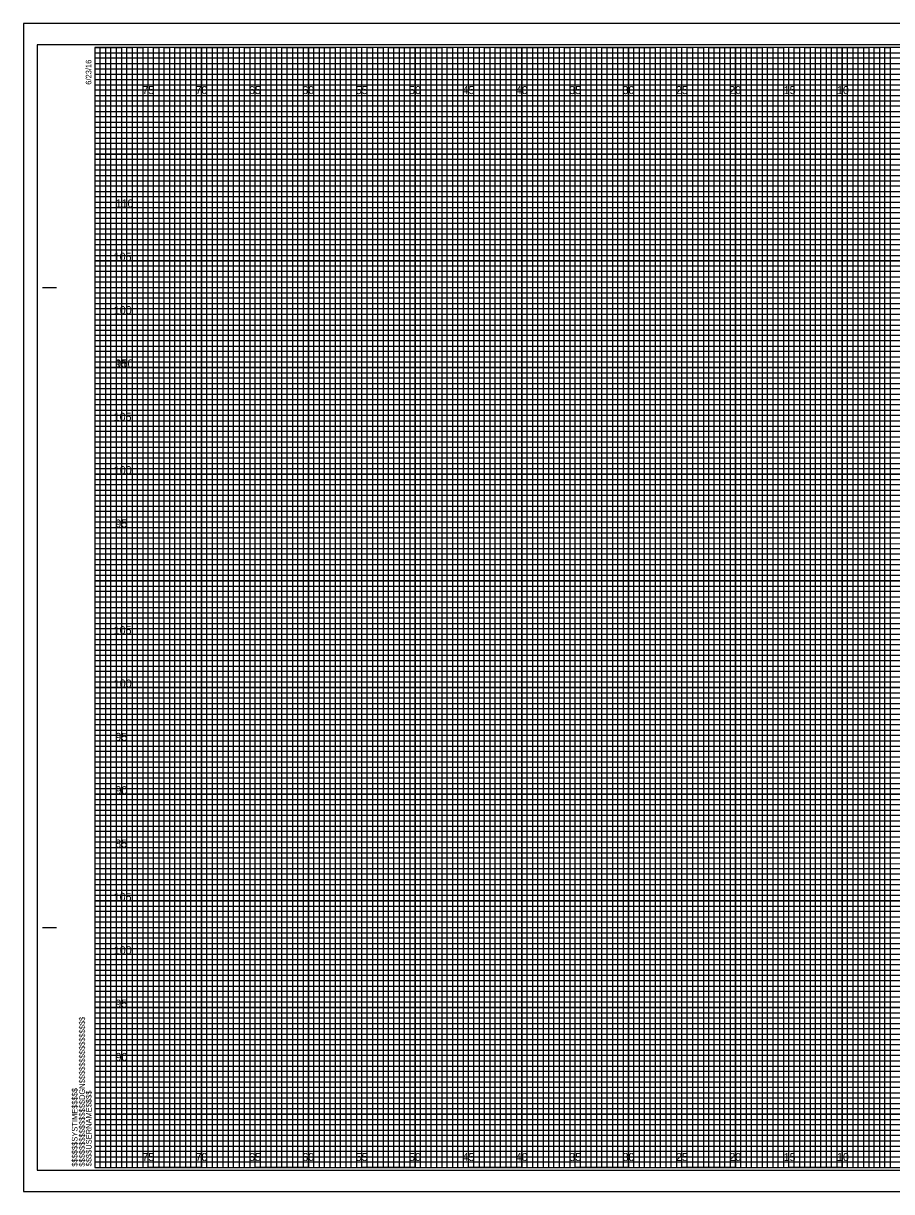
# Model space of a CAD drawing. Extents: x -7 to 182, y -2 to 1647.
# Drawn here: x -6.7 to 74.6, y 437.7 to 547.2 of the extents above; entities that cross this region are included whole.
import ezdxf

# ---------------------------------------------------------------- set-up
doc = ezdxf.new("R2010")
doc.units = 0
for name, color, linetype in [('Exist Cross Section Cell', 7, 'Continuous'), ('Exist XS Ground Line', 7, 'Continuous'), ('Prop CMT Pvmt Course 3', 7, 'Continuous'), ('Prop CMT Pvmt Wedge Surface 1', 7, 'Continuous'), ('Prop CMT Pvmt Wedge Surface 2', 7, 'Continuous'), ('Prop CMT Pvmt Wedge Surface 3', 7, 'Continuous'), ('Prop CMT Shld Paved Course 1', 7, 'Continuous'), ('Prop CMT Shld Paved Course 2', 7, 'Continuous'), ('Prop CMT Shld Paved Course 3', 7, 'Continuous'), ('Prop CMT Slope Grass', 7, 'Continuous'), ('Prop CMT Subgrade Earthwork', 7, 'Continuous')]:
    doc.layers.add(name, color=color, linetype=linetype)

msp = doc.modelspace()

# ---------------------------------------------------------------- linework, layer by layer
at = {"layer": 'Exist XS Ground Line'}
for p, q in [((5, 545), (0, 545)), ((5, 440), (5, 545)), ((15, 545), (10, 545)), ((10, 545), (10, 440)), ((15, 440), (15, 545)), ((25, 545), (20, 545)), ((20, 545), (20, 440)), ((25, 440), (25, 545)), ((35, 545), (30, 545)), ((30, 545), (30, 440)), ((35, 440), (35, 545)), ((45, 545), (40, 545)), ((40, 545), (40, 440)), ((45, 440), (45, 545)), ((55, 545), (50, 545)), ((50, 545), (50, 440)), ((55, 440), (55, 545)), ((65, 545), (60, 545)), ((60, 545), (60, 440)), ((65, 440), (65, 545)), ((75, 545), (70, 545)), ((70, 545), (70, 440)), ((10, 440), (5, 440)), ((20, 440), (15, 440)), ((30, 440), (25, 440)), ((40, 440), (35, 440)), ((50, 440), (45, 440)), ((60, 440), (55, 440)), ((70, 440), (65, 440))]:
    msp.add_line(p, q, dxfattribs=at)
for points in [[(0, 540), (160, 540), (160, 535), (0, 535)], [(0, 530), (160, 530), (160, 525), (0, 525)], [(0, 520), (160, 520), (160, 515), (0, 515)], [(0, 510), (160, 510), (160, 505), (0, 505)], [(0, 500), (160, 500), (160, 495), (0, 495)], [(0, 490), (160, 490), (160, 485), (0, 485)], [(0, 480), (160, 480), (160, 475), (0, 475)], [(0, 470), (160, 470), (160, 465), (0, 465)], [(0, 460), (160, 460), (160, 455), (0, 455)], [(0, 450), (160, 450), (160, 445), (0, 445)]]:
    msp.add_lwpolyline(points, dxfattribs=at)
at = {"layer": 'Prop CMT Pvmt Course 3'}
msp.add_lwpolyline([(-6.7, 437.75), (161.65, 437.75), (161.65, 547.25), (-6.7, 547.25)], close=True, dxfattribs=at)
at = {"layer": 'Prop CMT Pvmt Wedge Surface 1'}
for p, q in [((0, 544.5), (130, 544.5)), ((130, 543.99), (0, 543.99)), ((0, 543.99), (0, 543.5)), ((0, 543.5), (130, 543.5)), ((130, 542.95), (0, 542.95)), ((0, 542.95), (0, 542)), ((0, 542), (160, 542))]:
    msp.add_line(p, q, dxfattribs=at)
for points in [[(0, 541.5), (135, 541.5), (160, 541.5), (160, 541), (0, 541)], [(0, 540.5), (160, 540.5), (160, 539.5), (0, 539.5)], [(0, 539), (160, 539), (160, 538.5), (0, 538.49)], [(0, 538), (160, 538), (160, 537), (0, 537)], [(0, 536.5), (160, 536.5), (160, 536), (0, 536)], [(0, 535.5), (160, 535.5), (160, 534.5), (0, 534.5)], [(0, 534), (160, 534), (160, 533.5), (0, 533.5)], [(0, 533), (160, 533), (160, 532), (0, 532)], [(0, 531.5), (160, 531.5), (160, 531), (0, 531)], [(0, 530.5), (160, 530.5), (160, 529.5), (0, 529.5)], [(0, 529), (160, 529), (160, 528.5), (0, 528.5)], [(0, 528), (160, 528), (160, 526.98), (160, 526.5), (160, 526), (0, 526)], [(0, 527), (160, 527), (160, 526.5), (0, 526.5)], [(0, 525.5), (160, 525.5), (160, 524.5), (0, 524.51)], [(0, 524.51), (160, 524.5), (160, 524), (0, 524)], [(0, 523.5), (160, 523.5), (160, 523), (0, 523)], [(0, 522), (160, 522), (160, 521.5), (0, 521.5)], [(0, 521), (160, 521), (160, 520.5), (0, 520.5)], [(-0.04, 519.45), (160, 519.45), (160, 518.94), (-0.04, 518.94)], [(0, 518.5), (160, 518.5), (160, 518), (0, 518)], [(0, 517), (160, 517), (160, 516.5), (0, 516.5)], [(0, 516), (160, 516), (160, 515.5), (0, 515.5)], [(0, 514.5), (160, 514.5), (160, 514), (0, 514)], [(0, 513.5), (160, 513.5), (160, 513), (0, 513)], [(0, 512), (160, 512), (160, 511.5), (0, 511.5)], [(0, 511), (160, 511), (160, 510.5), (0, 510.5)], [(0, 509.5), (160, 509.5), (160, 508.99), (0, 509)], [(0, 508.5), (160, 508.5), (160, 508), (0, 508)], [(0, 507), (160, 507), (160, 506.5), (0, 506.5)], [(0, 506), (160, 506), (160, 505.5), (0, 505.5)], [(0, 504.5), (160, 504.5), (160, 504), (0, 504)], [(0, 503.5), (160, 503.5), (160, 503), (0, 503)], [(0, 502), (160, 502), (160, 501.5), (0, 501.5)], [(0, 501), (160, 501), (160, 500.5), (0, 500.5)], [(0, 499.5), (160, 499.5), (160, 499), (0, 499)], [(0, 498.5), (160.03, 498.45), (160, 498), (0, 498)], [(0, 497), (160, 497), (160, 496.5), (0, 496.5)], [(0, 496), (160, 496), (160, 495.5), (0, 495.5)], [(0, 494.5), (160, 494.5), (160, 494), (0, 494)], [(0, 493.5), (160, 493.5), (160, 493), (0, 493)], [(0, 492), (160, 492), (160, 491.5), (0, 491.5)], [(0, 491), (160, 491), (160, 490.5), (0, 490.5)], [(0, 489.5), (160, 489.5), (160, 489), (0, 489)], [(0, 488.5), (160, 488.5), (160, 488), (0, 488)], [(0, 487), (160, 487), (160, 486.5), (0, 486.5)], [(0, 486), (160, 486), (160, 485.5), (0, 485.5)], [(0, 484.5), (160, 484.5), (160, 484), (0, 484)], [(0, 483.5), (160, 483.5), (160, 483), (0, 483)], [(0, 482), (160, 482), (160, 481.5), (0, 481.5)], [(0, 481), (160, 481), (160, 480.5), (0, 480.5)], [(0, 479.5), (160, 479.5), (160, 478.99), (0, 479)], [(0, 478.5), (160, 478.5), (160, 478), (0, 478)], [(0, 477), (160, 477), (160, 476.5), (0, 476.5)], [(0, 476), (160, 476), (160, 475.5), (0, 475.5)], [(0, 474.5), (160, 474.5), (160, 474), (0, 474)], [(0, 473.5), (160, 473.5), (160, 473), (0, 473)], [(0, 472), (160, 472), (160, 471.5), (0, 471.5)], [(0, 471), (160, 471), (160, 470.5), (0, 470.5)], [(0, 469.5), (160, 469.5), (160, 469), (0, 469)], [(0, 468.5), (160.03, 468.45), (160, 468), (0, 468)], [(0, 467), (160, 467), (160, 466.5), (0, 466.5)], [(0, 466), (160, 466), (160, 465.5), (0, 465.5)], [(0, 464.5), (160, 464.5), (160, 464), (0, 464)], [(0, 463.5), (160, 463.5), (160, 463), (0, 463)], [(0, 462), (160, 462), (160, 461.5), (0, 461.5)], [(0, 461), (160, 461), (160, 460.5), (0, 460.5)], [(0, 459.5), (160, 459.5), (160, 459), (0, 459)], [(0, 458.5), (160, 458.5), (160, 458), (0, 458)], [(0, 457), (160, 457), (160, 456.5), (0, 456.5)], [(0, 456), (160, 456), (160, 455.5), (0, 455.5)], [(0, 454.5), (160, 454.5), (160, 454), (0, 454)], [(0, 453.5), (160, 453.5), (160, 453), (0, 453)], [(0, 452), (160, 452), (160, 451.5), (0, 451.5)], [(0, 451), (160, 451), (160, 450.5), (0, 450.5)], [(0, 449.5), (160, 449.5), (160, 449), (0, 449)], [(0, 448.5), (160, 448.5), (160, 448), (0, 448)], [(0, 447), (160, 447), (160, 446.5), (0, 446.5)], [(0, 446), (160, 446), (160, 445.5), (0, 445.5)], [(0, 444.5), (160, 444.5), (160, 444), (0, 444)], [(0, 443.5), (160, 443.5), (160, 443), (0, 443)], [(0, 442), (160, 442), (160, 441.5), (0, 441.5)], [(0, 441), (160, 441), (160, 440.5), (0, 440.5)]]:
    msp.add_lwpolyline(points, dxfattribs=at)
at = {"layer": 'Prop CMT Pvmt Wedge Surface 2'}
for p, q in [((-4.9, 522.5), (-3.65, 522.5)), ((-4.85, 522.5), (-3.6, 522.5)), ((-4.9, 462.5), (-3.65, 462.5)), ((-4.85, 462.5), (-3.6, 462.5)), ((0, 440), (0, 440)), ((0, 440), (0, 440)), ((0, 440), (0, 440)), ((0, 440), (0, 440)), ((0, 440), (0, 440)), ((0, 440), (0, 440)), ((0, 440), (0, 440))]:
    msp.add_line(p, q, dxfattribs=at)
msp.add_lwpolyline([(160, 545), (0, 545), (0, 440), (160, 440)], close=True, dxfattribs=at)
at = {"layer": 'Prop CMT Pvmt Wedge Surface 3'}
for points in [[(0, 440), (0.5, 440), (0.5, 545), (1, 545), (1, 440)], [(1, 440), (1.5, 440), (1.5, 545), (2, 545), (2, 440)], [(2.5, 440), (3, 440), (3, 545), (3.5, 545), (3.5, 440)], [(3.5, 440), (4, 440), (4, 545), (4.5, 545), (4.5, 440)], [(5, 440), (5.5, 440), (5.5, 545), (6, 545), (6, 440)], [(6, 440), (6.5, 440), (6.5, 545), (7, 545), (7, 440)], [(7.5, 440), (8, 440), (8, 545), (8.5, 545), (8.5, 440)], [(8.5, 440), (9, 440), (9, 545), (9.5, 545), (9.5, 440)], [(10, 440), (10.5, 440), (10.5, 545), (11, 545), (11, 440)], [(11, 440), (11.5, 440), (11.5, 545), (12, 545), (12, 440)], [(12.5, 440), (13, 440), (13, 545), (13.5, 545), (13.5, 440)], [(13.5, 440), (14, 440), (14, 545), (14.5, 545), (14.5, 440)], [(15, 440), (15.5, 440), (15.5, 545), (16, 545), (16, 440)], [(16, 440), (16.5, 440), (16.5, 545), (17, 545), (17, 440)], [(17.5, 440), (18, 440), (18, 545), (18.5, 545), (18.5, 440)], [(18.5, 440), (19, 440), (19, 545), (19.5, 545), (19.5, 440)], [(20, 440), (20.5, 440), (20.5, 545), (21, 545), (21, 440)], [(21, 440), (21.5, 440), (21.5, 545), (22, 545), (22, 440)], [(22.5, 440), (23, 440), (23, 545), (23.5, 545), (23.5, 440)], [(23.5, 440), (24, 440), (24, 545), (24.5, 545), (24.5, 440)], [(25, 440), (25.5, 440), (25.5, 545), (26, 545), (26, 440)], [(26, 440), (26.5, 440), (26.5, 545), (27, 545), (27, 440)], [(27.5, 440), (28, 440), (28, 545), (28.5, 545), (28.5, 440)], [(28.5, 440), (29, 440), (29, 545), (29.5, 545), (29.5, 440)], [(30, 440), (30.5, 440), (30.5, 545), (31, 545), (31, 440)], [(31, 440), (31.5, 440), (31.5, 545), (32, 545), (32, 440)], [(32.5, 440), (33, 440), (33, 545), (33.5, 545), (33.5, 440)], [(33.5, 440), (34, 440), (34, 545), (34.5, 545), (34.5, 440)], [(35, 440), (35.5, 440), (35.5, 545), (36, 545), (36, 440)], [(36, 440), (36.5, 440), (36.5, 545), (37, 545), (37, 440)], [(37.5, 440), (38, 440), (38, 545), (38.5, 545), (38.5, 440)], [(38.5, 440), (39, 440), (39, 545), (39.5, 545), (39.5, 440)], [(40, 440), (40.5, 440), (40.5, 545), (41, 545), (41, 440)], [(41, 440), (41.5, 440), (41.5, 545), (42, 545), (42, 440)], [(42.5, 440), (43, 440), (43, 545), (43.5, 545), (43.5, 440)], [(43.5, 440), (44, 440), (44, 545), (44.5, 545), (44.5, 440)], [(45, 440), (45.5, 440), (45.5, 545), (46, 545), (46, 440)], [(46, 440), (46.5, 440), (46.5, 545), (47, 545), (47, 440)], [(47.5, 440), (48, 440), (48, 545), (48.5, 545), (48.5, 440)], [(48.5, 440), (49, 440), (49, 545), (49.5, 545), (49.5, 440)], [(50, 440), (50.5, 440), (50.5, 545), (51, 545), (51, 440)], [(51, 440), (51.5, 440), (51.5, 545), (52, 545), (52, 440)], [(52.5, 440), (53, 440), (53, 545), (53.5, 545), (53.5, 440)], [(53.5, 440), (54, 440), (54, 545), (54.5, 545), (54.5, 440)], [(55, 440), (55.5, 440), (55.5, 545), (56, 545), (56, 440)], [(56, 440), (56.5, 440), (56.5, 545), (57, 545), (57, 440)], [(57.5, 440), (58, 440), (58, 545), (58.5, 545), (58.5, 440)], [(58.5, 440), (59, 440), (59, 545), (59.5, 545), (59.5, 440)], [(60, 440), (60.5, 440), (60.5, 545), (61, 545), (61, 440)], [(61, 440), (61.5, 440), (61.5, 545), (62, 545), (62, 440)], [(62.5, 440), (63, 440), (63, 545), (63.5, 545), (63.5, 440)], [(63.5, 440), (64, 440), (64, 545), (64.5, 545), (64.5, 440)], [(65, 440), (65.5, 440), (65.5, 545), (66, 545), (66, 440)], [(66, 440), (66.5, 440), (66.5, 545), (67, 545), (67, 440)], [(67.5, 440), (68, 440), (68, 545), (68.5, 545), (68.5, 440)], [(68.5, 440), (69, 440), (69, 545), (69.5, 545), (69.5, 440)], [(70, 440), (70.5, 440), (70.5, 545), (71, 545), (71, 440)], [(71, 440), (71.5, 440), (71.5, 545), (72, 545), (72, 440)], [(72.5, 440), (73, 440), (73, 545), (73.5, 545), (73.5, 440)], [(73.5, 440), (74, 440), (74, 545), (74.5, 545), (74.5, 440)]]:
    msp.add_lwpolyline(points, dxfattribs=at)
at = {"layer": 'Prop CMT Shld Paved Course 1'}
for p, q in [((5, 440), (5, 545)), ((10, 440), (10, 545)), ((15, 440), (15, 545)), ((20, 440), (20, 545)), ((25, 440), (25, 545)), ((30, 440), (30, 545)), ((35, 440), (35, 545)), ((40, 440), (40, 545)), ((45, 440), (45, 545)), ((50, 440), (50, 545)), ((55, 440), (55, 545)), ((60, 440), (60, 545)), ((65, 440), (65, 545)), ((70, 440), (70, 545)), ((0, 540), (160, 540)), ((0, 535), (160, 535)), ((0, 530), (160, 530)), ((0, 525), (160, 525)), ((0, 520), (160, 520)), ((0, 515), (160, 515)), ((0, 510), (160, 510)), ((0, 505), (160, 505)), ((0, 500), (160, 500)), ((0, 495), (160, 495)), ((0, 490), (160, 490)), ((0, 485), (160, 485)), ((0, 480), (160, 480)), ((0, 475), (160, 475)), ((0, 470), (160, 470)), ((0, 465), (160, 465)), ((0, 460), (160, 460)), ((0, 455), (160, 455)), ((0, 450), (160, 450)), ((0, 445), (160, 445))]:
    msp.add_line(p, q, dxfattribs=at)
at = {"layer": 'Prop CMT Shld Paved Course 2'}
for p, q in [((161.65, 547.25), (-6.7, 547.25)), ((-6.7, 547.25), (-6.7, 437.75)), ((-6.7, 437.75), (161.65, 437.75))]:
    msp.add_line(p, q, dxfattribs=at)
at = {"layer": 'Prop CMT Slope Grass'}
msp.add_lwpolyline([(-5.4, 439.75), (161.2, 439.75), (161.2, 545.25), (-5.4, 545.25)], close=True, dxfattribs=at)
at = {"layer": 'Prop CMT Subgrade Earthwork'}
for points in [[(0, 545), (2.5, 545), (2.5, 440), (7.5, 440), (7.5, 545), (12.5, 545), (12.5, 440), (17.5, 440), (17.5, 545), (22.5, 545), (22.5, 440), (27.5, 440), (27.5, 545), (32.5, 545), (32.5, 440), (37.5, 440), (37.5, 545), (42.5, 545), (42.5, 440), (47.5, 440), (47.5, 545), (52.5, 545), (52.5, 440), (57.5, 440), (57.5, 545), (62.5, 545), (62.5, 440), (67.5, 440), (67.5, 545), (72.5, 545), (72.5, 440), (77.5, 440)], [(0, 542.5), (137.5, 542.5)], [(0, 532.5), (160, 532.5), (160, 537.5), (0, 537.5)], [(0, 522.5), (160, 522.5), (160, 527.5), (0, 527.5)], [(0, 512.5), (160, 512.5), (160, 517.5), (0, 517.5)], [(0, 502.5), (160, 502.5), (160, 507.5), (0, 507.5)], [(0, 492.5), (160, 492.5), (160, 497.5), (0, 497.5)], [(0, 482.5), (160, 482.5), (160, 487.5), (0, 487.5)], [(0, 472.5), (160, 472.5), (160, 477.5), (0, 477.5)], [(0, 462.5), (160, 462.5), (160, 467.5), (0, 467.5)], [(0, 452.5), (160, 452.5), (160, 457.5), (0, 457.5)], [(0, 442.5), (160, 442.5), (160, 447.5), (0, 447.5)]]:
    msp.add_lwpolyline(points, dxfattribs=at)

# ---------------------------------------------------------------- texts
at = {"layer": 'Exist Cross Section Cell'}
for s, p in [('75', (4.44, 540.62)), ('70', (9.43, 540.62)), ('65', (14.44, 540.62)), ('60', (19.43, 540.62)), ('55', (24.44, 540.62)), ('50', (29.43, 540.62)), ('45', (34.44, 540.62)), ('40', (39.43, 540.62)), ('35', (44.44, 540.62)), ('30', (49.43, 540.62)), ('25', (54.44, 540.62)), ('20', (59.43, 540.62)), ('15', (64.53, 540.62)), ('10', (69.52, 540.62)), ('75', (4.44, 440.62)), ('70', (9.43, 440.62)), ('65', (14.44, 440.62)), ('60', (19.43, 440.62)), ('55', (24.44, 440.62)), ('50', (29.43, 440.62)), ('45', (34.44, 440.62)), ('40', (39.43, 440.62)), ('35', (44.44, 440.62)), ('30', (49.43, 440.62)), ('25', (54.44, 440.62)), ('20', (59.43, 440.62)), ('15', (64.53, 440.62)), ('10', (69.52, 440.62))]:
    msp.add_text(s, height=0.75, dxfattribs=at).set_placement(p)
at = {"layer": 'Prop CMT Pvmt Wedge Surface 2'}
for s, p in [('6/23/16', (-0.33, 541.5)), ('$$$$$$$$$$$$$$$$DGN$$$$$$$$$$$$$$$$', (-0.94, 440.09)), ('$$$$$$SYSTIME$$$$$', (-1.63, 440.09)), ('$$$$USERNAME$$$$', (-0.31, 440.12))]:
    msp.add_text(s, height=0.525, rotation=90, dxfattribs=at).set_placement(p)
at = {"layer": 'Prop CMT Shld Paved Course 3'}
for s, p in [('110', (1.94, 530)), ('105', (1.76, 525)), ('100', (1.77, 520)), ('95', (1.92, 515)), ('110', (1.94, 515)), ('105', (1.76, 510)), ('100', (1.77, 505)), ('95', (1.92, 500)), ('105', (1.76, 490)), ('100', (1.77, 485)), ('95', (1.92, 480)), ('90', (1.93, 475)), ('85', (1.91, 470)), ('105', (1.76, 465)), ('100', (1.77, 460)), ('95', (1.92, 455)), ('90', (1.93, 450))]:
    msp.add_text(s, height=0.75, dxfattribs=at).set_placement(p)

doc.saveas('drawing.dxf')
